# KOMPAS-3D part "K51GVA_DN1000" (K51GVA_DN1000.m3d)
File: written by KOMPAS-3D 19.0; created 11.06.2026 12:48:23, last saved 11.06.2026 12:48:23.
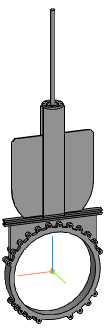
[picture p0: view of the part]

Document properties: Автор: Энергия; Полное имя файла: Z:\3.Личные\kachalov\001_3d для проектировщиков\2.6 Тип_K51GVA. Задвижка\_stp\_stp_K51GVA_DN50-DN1000_с фланцем\K51GVA_DN1000.m3d

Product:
- Part/product: K51GVA_DN1000

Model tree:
1. Операция без истории:1  (labels: K51GVA_DN1000)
